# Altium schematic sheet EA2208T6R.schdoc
size 127 x 101 mm
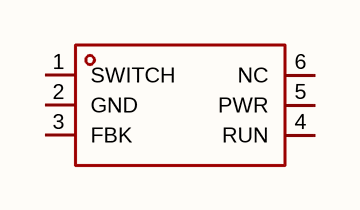
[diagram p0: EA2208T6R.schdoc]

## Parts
U?  ea2208t6r  [SOT-23-6_L2.9-W1.6-P0.95-LS2.8-BR]  (value not drawn)

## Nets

Not connected (* = marked no-connect by the designer): U? 1(SWITCH) 2(GND) 3(FBK) 4(RUN) 5(PWR) 6(NC)

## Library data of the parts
U? = ea2208t6r: 功能类型:升压型;工作电压:2V~24V;输出电压:600mV~28V;输出电流:3A;输出类型:可调;; Manufacturer: everanalog(申风); AddInBom: yes; ModelId: 18da8f6c14a34920b3e136b5c401a119; ModelName: SOT-23-6_L2.9-W1.6-H1.5-LS2.8-P0.95; ModelTransform: 110.73671,114.173,0,180,0,0,0.001,-0.003,0; Function: 升压型; Voltage - Supply: 2V~24V; Output Current: 3A; Frequency - Switching: 1.2MHz; Synchronous Rectifier: 否; Number of Outputs: 1; Topology: 升压式; Quiescent Current: 100uA; Switch tube (built-in/external): 内置; Output Type: 可调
